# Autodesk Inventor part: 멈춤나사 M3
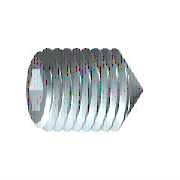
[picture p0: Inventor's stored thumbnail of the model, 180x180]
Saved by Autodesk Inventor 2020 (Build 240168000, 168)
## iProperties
Created: 2012-02
Part Number: 멈춤나사 M3
Material: 강철, 연강
Description: 6각 소켓 머리 없는 멈춤 나사
Document SubType Name: Modeling
Standard: KS B 1028
Designer: mduedu
Standards Organization: KS
Language: ko-KR
Size Designation: 원추점 M3x8
Categories: <MemberInstance><Categories><Category DisplayName="조임쇠" InternalName="e4da775c-781d-43d5-af7c-5136215cf5a6" Mnemonic="FSTN"><Category DisplayName="볼트" InternalN
Density: 7.86 g/cm^3
Mass: 0.360339 g
Surface Area: 0.888172 cm^2
Volume: 0.0458447 cm^3
Appearance: 노란색
IsCustomPart: 1
Author: mduedu
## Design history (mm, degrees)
sketch "스케치1"
  geometry: L1 (0, 0)-(5.5, 0); L2 (8, 0.866)-(8, 1.5); L3 (8, 1.5)-(0, 1.5); L4 (8, 0.866)-(6, 0.866); L5 (6, 0.866)-(5.5, 0); L6 (0, -0.3)-(0, 1.8) reference; L7 (0, 1.5)-(0, 0)
  constraints: 13 end point, 3 parallel, 1 collinear, 1 perpendicular, 1 point on line
  dimensions: "d0" = 2 distance of L2.start L4.end (= INTI); "d1" = 60 deg angle of L5 L1; "d2" = 3 diameter of L3 L1 (= NND); "d3" = 1.73205 diameter of L4 L1 (= 1.1547 x SW); "d5" = 8 distance from line of L2 L3.end (= NLG)
revolve "본체" sketch "스케치1" stored, may be unused: angle "d6" = 90 deg
sketch "스케치2"
  geometry: L1 (-0.433, 0.75)-(0.433, 0.75); L2 (0.433, 0.75)-(0.866, 0); L3 (0.866, 0)-(0.433, -0.75); L4 (0.433, -0.75)-(-0.433, -0.75); L5 (-0.433, -0.75)-(-0.866, 0); L6 (-0.866, 0)-(-0.433, 0.75); 3 further points
  constraints: 12 end point, 1 coincident, 1 horizontal, 13 other
extrude "슬롯" join sketch "스케치2" taper "d7" = 0 deg; stored distance "d21" = 10
workaxis "Work Axis1"
workplane "Work Plane1"
sketch "스케치5"
  geometry: L1 (-4, -0.15)-(-2.65, -1.5) reference; L2 (-4, 0.15)-(-2.65, 1.5) reference; L3 (-2.65, 1.5)-(-4.15, 0); L4 (-2.65, -1.5)-(-4.15, 0); 1 further point
  constraints: 4 end point, 1 horizontal alignment, 1 perpendicular
node "작업점1"
body "Solid1"
feature "스레드" dims "d12" = 8 (= NLG), "d13" = 0
chamfer "모따기1" distance "d8" = 1.35 (computed from NND, SPD, FAWI); stored, may be unused: angle "d9" = 45 deg (= FAWI), second distance "d34" = 1.35 (computed from NND, SPD, FAWI)
chamfer "모따기2" distance "d10" = 0.30673 (= -0.5 x GD1 + 0.5 x NND); stored, may be unused: angle "d11" = 45 deg (= FAWI), second distance "d35" = 0.30673 (= -0.5 x GD1 + 0.5 x NND)
other parameters: "NND" = 3 [user parameter; used in 5 equation terms], "NLG" = 8 [user parameter; used in 2 equation terms], "INTI" = 2 [user parameter; used in 1 equation term], "FAWI" = 45 deg [user parameter; used in 4 equation terms], "SW" = 1.5 [user parameter; used in 2 equation terms], "GD1" = 2.38655 (= THREADDIA - 1.2269 x PTC) [user parameter; used in 2 equation terms], "d4" = 0, "FAWI1" = 45 deg [user parameter], "SPD" = 0.3 [user parameter; used in 2 equation terms], "d36" = 0, "d37" = 0, "GUL" = 0.30673 (= 0.61345 x PTC) [user parameter], "TOA" = 30 deg [user parameter], "THREADDIA" = 3 [user parameter; used in 1 equation term], "PTC" = 0.5 [user parameter; used in 4 equation terms], "GAL" = 0.30673 (= 0.61345 x PTC) [user parameter], "E0" = 1.7325 (= 1.155 x SW) [user parameter]
